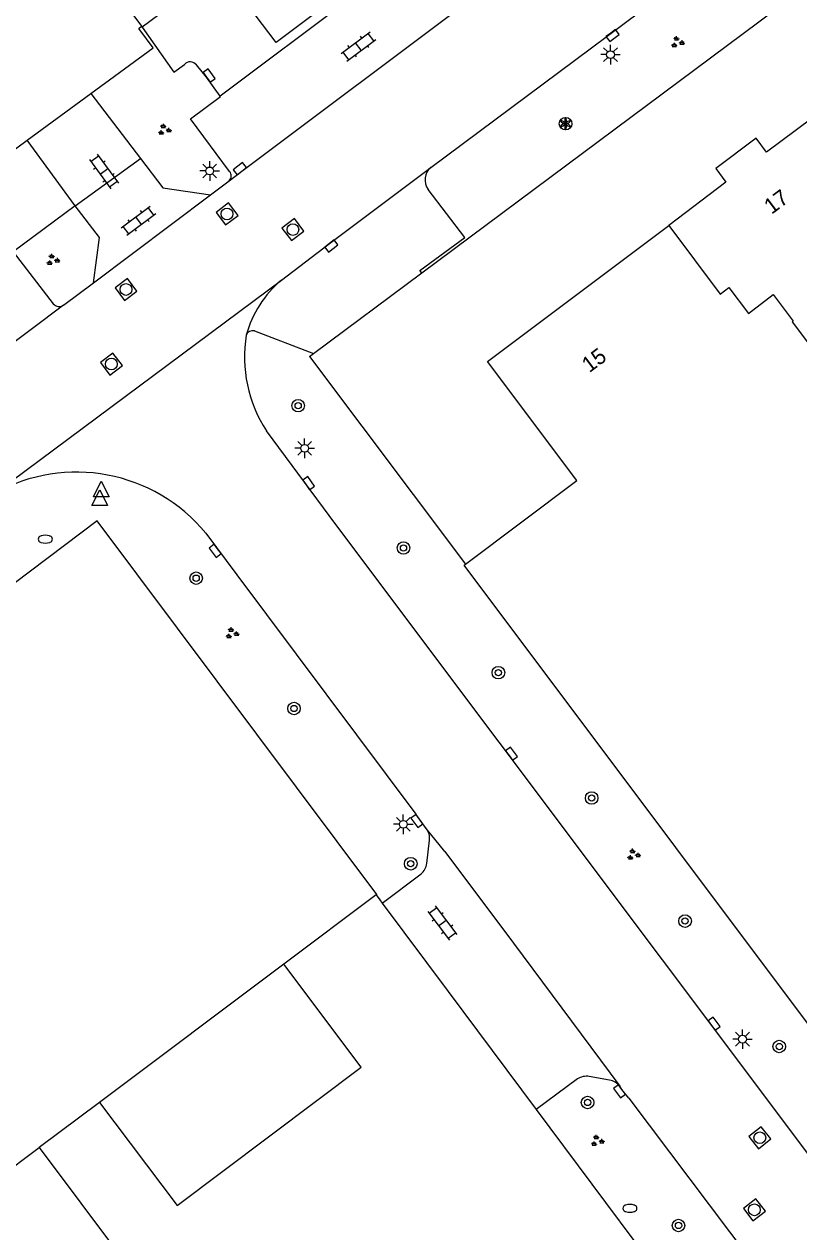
# Model space of a CAD drawing. Extents: x 130998 to 133001, y 398999 to 403002.
# Drawn here: x 131667.2 to 131716.6, y 400300.1 to 400377.1 of the extents above; entities that cross this region are included whole.
import ezdxf

# ---------------------------------------------------------------- set-up
doc = ezdxf.new("R2010")
doc.units = 0
for name, color, linetype in [('gg-afsc-hekwerk', 7, 'Continuous'), ('gg-anno-huisnummerreeks BGT', 7, 'Continuous'), ('gg-bbg-gedigitaliseerde bebouwing', 7, 'Continuous'), ('gg-bbg-hoofdgebouw', 7, 'Continuous'), ('gg-bbg-luifel en loopbrug', 7, 'Continuous'), ('gg-bbg-tussenscheiding', 7, 'Continuous'), ('gg-knt-verharding', 7, 'Continuous'), ('gg-knt-verharding nz', 7, 'Continuous'), ('gt-grn-weggrens', 7, 'Continuous'), ('gt-symb-boom', 7, 'Continuous'), ('gt-symb-brandkraan', 7, 'Continuous'), ('gt-symb-groenvak', 7, 'Continuous'), ('gt-symb-klinker verharding', 7, 'Continuous'), ('gt-symb-kolk', 7, 'Continuous'), ('gt-symb-lichtmast', 7, 'Continuous'), ('gt-symb-rioolschacht', 7, 'Continuous'), ('gt-symb-solitaire heester', 7, 'Continuous'), ('gt-symb-waterafsluiter', 7, 'Continuous')]:
    doc.layers.add(name, color=color, linetype=linetype)

# ---------------------------------------------------------------- blocks, each defined once
blk = doc.blocks.new('gt0-LMAST')
at = {"layer": 'gt-symb-lichtmast'}
for p, q in [((-0.182, 0.173), (-0.447, 0.438)), ((-0.005, 0.246), (-0.005, 0.621)), ((0.172, 0.173), (0.437, 0.438)), ((-0.255, -0.004), (-0.63, -0.004)), ((-0.182, -0.181), (-0.447, -0.446)), ((-0.005, -0.254), (-0.005, -0.629)), ((0.437, -0.446), (0.172, -0.181)), ((0.245, -0.004), (0.62, -0.004))]:
    blk.add_line(p, q, dxfattribs=at)
blk.add_circle((-0.005, -0.004), 0.25, dxfattribs=at)
blk = doc.blocks.new('gt0-GRVAK')
at = {"layer": 'gt-symb-groenvak'}
for p, q in [((-0.11, 0.189), (-0.228, 0.24)), ((-0.182, 0.153), (0.088, 0.153)), ((-0.091, 0.211), (-0.156, 0.322)), ((-0.047, 0.214), (-0.047, 0.393)), ((-0.004, 0.211), (0.061, 0.322)), ((0.015, 0.189), (0.133, 0.24)), ((0.262, -0.052), (0.197, 0.059)), ((0.305, -0.049), (0.305, 0.13)), ((0.349, -0.052), (0.414, 0.059)), ((-0.245, -0.228), (-0.363, -0.177)), ((-0.318, -0.264), (-0.047, -0.264)), ((-0.226, -0.206), (-0.291, -0.095)), ((-0.183, -0.203), (-0.183, -0.024)), ((-0.139, -0.206), (-0.074, -0.095)), ((-0.12, -0.228), (-0.002, -0.177)), ((0.243, -0.074), (0.125, -0.023)), ((0.17, -0.11), (0.441, -0.11)), ((0.368, -0.074), (0.486, -0.023))]:
    blk.add_line(p, q, dxfattribs=at)
blk = doc.blocks.new('gt0-KOLK')
at = {"layer": 'gt-symb-kolk'}
blk.add_lwpolyline([(0, 0), (0.375, 0), (0.375, 0.4), (-0.375, 0.4), (-0.375, 0), (0, 0)], dxfattribs=at)
blk = doc.blocks.new('gt0-BOOM')
at = {"layer": 'gt-symb-boom'}
for radius in [0.4, 0.2]:
    blk.add_circle((0, 0), radius, dxfattribs=at)
blk = doc.blocks.new('gt0-RS')
at = {"layer": 'gt-symb-rioolschacht'}
blk.add_lwpolyline([(-0.5, -0.5), (0.5, -0.5), (0.5, 0.5), (-0.5, 0.5)], close=True, dxfattribs=at)
blk.add_circle((0, 0), 0.375, dxfattribs=at)
blk = doc.blocks.new('gt0-BR')
at = {"layer": 'gt-symb-brandkraan'}
for centre, radius, start, end in [((-0.244, 0), 0.206, 107.56694, 252.43307), ((0.599, -2.664), 3, 106.89205, 107.56694), ((0, -0.691), 0.938, 73.10799, 106.89205), ((-0.599, -2.664), 3, 72.43309, 73.10799), ((0.244, 0), 0.206, 287.56695, 72.43309), ((0.599, 2.664), 3, 252.43307, 253.10797), ((0, 0.691), 0.938, 253.10797, 286.89206), ((-0.599, 2.664), 3, 286.89206, 287.56695)]:
    blk.add_arc(centre, radius, start, end, dxfattribs=at)
blk = doc.blocks.new('gt0-KL1')
at = {"layer": 'gt-symb-klinker verharding'}
for p, q in [((-1.15, 0.3), (1.15, 0.3)), ((-1, -0.3), (-1, 0.3)), ((-0.5, 0.3), (-0.5, 0.45)), ((0, -0.3), (0, 0.3)), ((0.5, 0.3), (0.5, 0.45)), ((1, -0.3), (1, 0.3)), ((-1.15, -0.3), (1.15, -0.3)), ((-0.5, -0.45), (-0.5, -0.3)), ((0.5, -0.45), (0.5, -0.3))]:
    blk.add_line(p, q, dxfattribs=at)
blk = doc.blocks.new('gt0-SH')
at = {"layer": 'gt-symb-solitaire heester'}
blk.add_circle((0, 0), 0.4, dxfattribs=at)
for centre, start, end in [((-0.346, 0.2), 270, 30), ((-0.346, -0.2), 330, 90), ((0, 0.4), 210, 330), ((0.346, 0.2), 150, 270), ((0.346, -0.2), 90, 210), ((0, -0.4), 30, 150)]:
    blk.add_arc(centre, 0.4, start, end, dxfattribs=at)
blk = doc.blocks.new('gt0-WAFSL')
at = {"layer": 'gt-symb-waterafsluiter'}
for p, q in [((-0.5, -0.333), (0, 0.667)), ((0, 0.667), (0.5, -0.333)), ((0.5, -0.333), (-0.5, -0.333))]:
    blk.add_line(p, q, dxfattribs=at)

msp = doc.modelspace()

# ---------------------------------------------------------------- linework, layer by layer
at = {"layer": 'gg-afsc-hekwerk'}
for p, q in [((131692.538, 400361.215), (131722.154, 400383.284)), ((131667.374, 400369.673), (131671.438, 400372.649)), ((131665.374, 400368.208), (131667.374, 400369.673)), ((131685.647, 400356.079), (131692.538, 400361.215)), ((131685.394, 400355.891), (131685.647, 400356.079)), ((131685.394, 400355.891), (131695.338, 400342.636)), ((131689.64, 400321.55), (131689.879, 400321.229)), ((131689.879, 400321.229), (131690.025, 400321.033)), ((131690.025, 400321.033), (131694.223, 400315.403)), ((131694.223, 400315.403), (131699.847, 400307.861)), ((131699.847, 400307.861), (131710.562, 400293.491))]:
    msp.add_line(p, q, dxfattribs=at)
msp.add_lwpolyline([(131671.438, 400372.649), (131675.424, 400375.568), (131674.494, 400376.808), (131674.678, 400376.946)], dxfattribs=at)
at = {"layer": 'gg-bbg-gedigitaliseerde bebouwing'}
msp.add_line((131648.92, 400411.328), (131674.678, 400376.946), dxfattribs=at)
at = {"layer": 'gg-bbg-hoofdgebouw'}
for p, q in [((131674.72, 400376.89), (131674.678, 400376.946)), ((131689.64, 400321.55), (131683.748, 400317.136)), ((131689.68, 400321.58), (131689.64, 400321.55)), ((131683.748, 400317.136), (131671.988, 400308.326)), ((131671.988, 400308.326), (131668.155, 400305.454)), ((131668.155, 400305.454), (131689.118, 400277.419))]:
    msp.add_line(p, q, dxfattribs=at)
for points in [[(131708.083, 400394.559), (131683.26, 400375.9), (131679.71, 400380.6), (131674.72, 400376.89)], [(131718.36, 400371.75), (131714.538, 400368.923), (131713.87, 400369.796), (131711.288, 400367.871), (131711.945, 400366.989), (131708.303, 400364.227)], [(131695.338, 400342.636), (131702.43, 400347.97), (131696.73, 400355.57), (131708.303, 400364.227)], [(131689.68, 400321.58), (131671.85, 400345.4), (131665.477, 400340.627)], [(131722.272, 400306.594), (131722.24, 400306.57), (131695.25, 400342.57), (131695.338, 400342.636)]]:
    msp.add_lwpolyline(points, dxfattribs=at)
at = {"layer": 'gg-bbg-luifel en loopbrug'}
msp.add_lwpolyline([(131671.988, 400308.326), (131676.943, 400301.741), (131688.685, 400310.576), (131683.748, 400317.136)], dxfattribs=at)
at = {"layer": 'gg-bbg-tussenscheiding'}
msp.add_line((131661.84, 400300.727), (131668.155, 400305.454), dxfattribs=at)
msp.add_lwpolyline([(131708.303, 400364.227), (131711.572, 400359.866), (131712.132, 400360.286), (131713.371, 400358.634), (131714.963, 400359.828), (131716.232, 400358.136), (131716.172, 400358.091), (131725.742, 400345.325), (131722.529, 400342.917), (131739.881, 400319.771)], dxfattribs=at)
at = {"layer": 'gg-knt-verharding'}
for p, q in [((131695.724, 400384.521), (131679.698, 400372.477)), ((131671.438, 400372.649), (131674.603, 400368.508)), ((131670.438, 400365.499), (131667.374, 400369.673)), ((131679.064, 400366.185), (131680.253, 400367.079)), ((131695.284, 400363.461), (131692.947, 400366.54)), ((131670.438, 400365.499), (131666.493, 400362.554)), ((131666.493, 400362.554), (131669.047, 400359.236)), ((131669.688, 400359.147), (131671.603, 400360.588)), ((131681.87, 400357.52), (131685.647, 400356.079)), ((131687.059, 400345.165), (131682.64, 400351.135)), ((131724.587, 400295.148), (131687.059, 400345.165)), ((131678.772, 400344.612), (131680.75, 400341.969)), ((131680.75, 400341.969), (131692.168, 400326.702)), ((131692.828, 400325.79), (131692.168, 400326.702)), ((131692.862, 400323.556), (131693.034, 400325.04)), ((131690.025, 400321.033), (131692.498, 400322.893)), ((131702.466, 400309.82), (131699.847, 400307.861)), ((131704.516, 400309.732), (131703.227, 400309.974)), ((131705.741, 400308.597), (131716.562, 400294.254))]:
    msp.add_line(p, q, dxfattribs=at)
for points in [[(131693.122, 400367.943), (131714.613, 400383.969), (131715.67, 400384.771)], [(131674.72, 400376.89), (131676.739, 400374.016), (131677.409, 400374.501)], [(131679.698, 400372.477), (131678.826, 400373.689), (131678.174, 400374.471)], [(131680.289, 400367.681), (131677.794, 400371.031), (131679.71, 400372.461), (131679.698, 400372.477)], [(131674.603, 400368.508), (131676.028, 400366.644), (131679.064, 400366.185)], [(131671.603, 400360.588), (131672.001, 400363.461), (131670.438, 400365.499)], [(131692.538, 400361.215), (131692.43, 400361.36), (131695.284, 400363.461)], [(131705.741, 400308.597), (131705.313, 400309.149), (131705.179, 400309.348)]]:
    msp.add_lwpolyline(points, dxfattribs=at)
for centre, radius, start, end in [((131677.78, 400374.203), 0.476, 34.20614, 141.30237), ((131693.782, 400367.148), 1.033, 129.69149, 216.08864), ((131679.975, 400367.398), 0.423, 311.13987, 42.01563), ((131669.421, 400359.579), 0.508, 222.52508, 301.66547), ((131689.879, 400355.85), 8.639, 170.67466, 213.0781), ((131681.777, 400357.069), 0.46, 78.39229, 156.84986), ((131670.523, 400337.833), 10.677, 39.41096, 119.2403), ((131692.046, 400325.172), 0.996, 352.38622, 38.33077), ((131691.882, 400323.663), 0.986, 308.67508, 353.78962), ((131703.056, 400308.862), 1.125, 81.24655, 121.63381), ((131704.388, 400308.746), 0.994, 37.25667, 82.58573)]:
    msp.add_arc(centre, radius, start, end, dxfattribs=at)
at = {"layer": 'gg-knt-verharding nz'}
for p, q in [((131681.066, 400367.702), (131696.544, 400379.31)), ((131680.253, 400367.079), (131681.066, 400367.702)), ((131671.603, 400360.588), (131679.064, 400366.185)), ((131669.688, 400359.147), (131661.514, 400352.999)), ((131694.009, 400324.31), (131692.828, 400325.79)), ((131694.009, 400324.31), (131698.39, 400318.472)), ((131698.39, 400318.472), (131705.179, 400309.348))]:
    msp.add_line(p, q, dxfattribs=at)
msp.add_lwpolyline([(131683.589, 400360.753), (131686.656, 400363.088), (131693.122, 400367.943)], dxfattribs=at)
msp.add_arc((131688.151, 400355.378), 7.05, 130.32251, 164.59974, dxfattribs=at)
at = {"layer": 'gt-grn-weggrens'}
for p, q in [((131670.438, 400365.499), (131674.603, 400368.508)), ((131665.307, 400347.15), (131683.589, 400360.753))]:
    msp.add_line(p, q, dxfattribs=at)

# ---------------------------------------------------------------- block references
at = {"layer": 'gt-symb-boom'}
for p in [(131684.663, 400352.749), (131691.379, 400343.676), (131678.157, 400341.746), (131697.432, 400335.726), (131684.397, 400333.439), (131703.381, 400327.729), (131691.84, 400323.54), (131709.337, 400319.882), (131715.34, 400311.883), (131703.117, 400308.318), (131708.919, 400300.476)]:
    msp.add_blockref('gt0-BOOM', p, dxfattribs=at)
at = {"layer": 'gt-symb-brandkraan'}
for p in [(131668.538, 400344.234), (131705.818, 400301.567)]:
    msp.add_blockref('gt0-BR', p, dxfattribs=at)
at = {"layer": 'gt-symb-groenvak'}
for p in [(131708.838, 400375.917), (131676.112, 400370.335), (131668.999, 400362.036), (131680.43, 400338.227), (131706.037, 400324.108), (131703.723, 400305.863)]:
    msp.add_blockref('gt0-GRVAK', p, dxfattribs=at)
at = {"layer": 'gt-symb-klinker verharding'}
for p, rotation in [((131688.507, 400375.649), 36.86989764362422), ((131672.276, 400367.685), -54.069481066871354), ((131674.482, 400364.543), 36.86989764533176), ((131693.857, 400319.764), -53.13010235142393)]:
    msp.add_blockref('gt0-KL1', p, dxfattribs=dict(at, rotation=rotation))
at = {"layer": 'gt-symb-kolk'}
for p, rotation in [((131704.593, 400376.504), -143.25620330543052), ((131678.826, 400373.689), -54.24239066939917), ((131681.066, 400367.702), 37.44283634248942), ((131686.656, 400363.088), -142.5199776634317), ((131685.17, 400347.691), -54.768642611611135), ((131679.522, 400343.614), 127.11068297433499), ((131698.108, 400330.442), -52.79798982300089), ((131692.4, 400326.382), 125.80410590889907), ((131711.027, 400313.221), -53.13010235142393), ((131705.313, 400309.149), 127.80965211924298)]:
    msp.add_blockref('gt0-KOLK', p, dxfattribs=dict(at, rotation=rotation))
at = {"layer": 'gt-symb-lichtmast'}
for p in [(131704.586, 400375.136), (131679.023, 400367.719), (131685.078, 400350.033), (131691.37, 400326.059), (131713.003, 400312.356)]:
    msp.add_blockref('gt0-LMAST', p, dxfattribs=at)
at = {"layer": 'gt-symb-rioolschacht'}
for p, rotation in [((131680.124, 400364.973), 37.568592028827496), ((131684.326, 400363.978), 37.3169744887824), ((131673.682, 400360.158), 36.95012773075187), ((131672.75, 400355.402), 37.6489164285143), ((131714.103, 400306.066), -51.08960261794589), ((131713.758, 400301.473), -52.6374693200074)]:
    msp.add_blockref('gt0-RS', p, dxfattribs=dict(at, rotation=rotation))
at = {"layer": 'gt-symb-solitaire heester'}
msp.add_blockref('gt0-SH', (131701.714, 400370.729), dxfattribs=at)
at = {"layer": 'gt-symb-waterafsluiter'}
for p in [(131672.103, 400347.264), (131672.003, 400346.714)]:
    msp.add_blockref('gt0-WAFSL', p, dxfattribs=at)

# ---------------------------------------------------------------- texts
at = {"layer": 'gg-anno-huisnummerreeks BGT'}
for s, rotation, p in [('17', 36.7, (131714.85, 400364.914)), ('15', 36.8, (131703.228, 400354.812))]:
    msp.add_text(s, height=1, rotation=rotation, dxfattribs=at).set_placement(p)

doc.saveas('drawing.dxf')
